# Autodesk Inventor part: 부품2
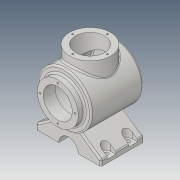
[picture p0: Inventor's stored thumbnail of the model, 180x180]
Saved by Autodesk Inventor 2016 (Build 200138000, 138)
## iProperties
Created: 2017-04
Part Number: 부품2
Material: Generic
Document SubType Name: Modeling
Designer: Administrator
Density: 1 g/cm^3
Appearance: 눈
Author: Administrator
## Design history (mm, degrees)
sketch "스케치1"
  geometry: L1 (-60, 2.834)-(-60, 12.834); L2 (-60, 12.834)-(-17.156, 42.834); L3 (-17.156, 42.834)-(17.156, 42.834); L4 (17.156, 42.834)-(60, 12.834); L5 (60, 12.834)-(60, 2.834); L6 (60, 2.834)-(-60, 2.834); 1 further point
  constraints: 12 end point, 2 perpendicular, 1 parallel, 1 vertical
  dimensions: "d0" = 120 distance of L5.end L1.start; "d1" = 10 distance of L4.end L5.end; "d2" = 10 distance of L1.start L1.end; "d3" = 55 deg angle of L2 L1; "d4" = 55 deg angle of L5 L4; "d5" = 40 distance between parallel lines of L6 L3; "d25" = 60 distance from line of point (0, 0) L1
extrude "돌출1" new body sketch "스케치1" stored distance "d6" = 80; taper "d7" = 0 deg
sketch "스케치2"
  geometry: L1 (42.834, -40)-(2.834, -40) reference; L2 (2.834, -40)-(2.834, 40) reference; L3 (2.834, 40)-(42.834, 40) reference; L4 (42.834, 40)-(42.834, -40) reference; L5 (84.834, -60)-(84.834, 48); L6 (84.834, 48)-(134.834, 48); L7 (134.834, 48)-(134.834, -47.617); L8 (134.834, -60)-(84.834, -60); L9 (116.006, 53)-(59.177, 53); L10 (84.834, 48)-(84.834, 65.284); A1 r 113 centre (84.037, 53.322) between (84.834, -59.675) and (134.834, -47.617); 1 further point
  constraints: 12 end point, 3 perpendicular, 2 point on circle, 2 vertical, 1 centre point, 1 horizontal, 1 point on line
  dimensions: "d8" = 108 distance of L6.end L8.start; "d9" = 82 distance between parallel lines of L2 L5; "d10" = 100 diameter of L7 L5; "d11" = 8 distance between parallel lines of L3 L6; "d12" = 113 distance between parallel lines of L8 L9; "d16" = 113 radius of A1
revolve "회전1" sketch "스케치2" stored, may be unused: angle "d17" = 90 deg
sketch "스케치3"
  geometry: C1 r 50 at (0, 0) reference; C2 r 38 at (0, 0); 1 further point
  constraints: 1 centre point, 1 coincident
  dimensions: "d18" = 76 diameter of C2
extrude "돌출2" join sketch "스케치3" distance "d19" = 12; taper "d20" = 0 deg
node "작업 평면1"
sketch "스케치4"
  geometry: C1 r 38 at (60, -40); 1 further point
  constraints: 1 centre point, 1 coincident
  dimensions: "d22" = 76 diameter of C1
extrude "돌출3" join sketch "스케치4" stored distance "d23" = 12; taper "d24" = 0 deg
sketch "스케치5"
  geometry: L1 (-21.584, 39.732)-(-60, 12.834) reference; L2 (-60, 12.834)-(-60, 2.834) reference; L3 (-60, 2.834)-(60, 2.834) reference; L4 (60, 2.834)-(60, 12.834) reference; L5 (60, 12.834)-(21.584, 39.732) reference; A1 r 50 centre (0, 84.834) between (-21.584, 39.732) and (21.584, 39.732) reference; 1 further point
sketch "스케치6"
  geometry: L1 (-60, 2.834)-(60, 2.834) reference; C1 r 18 at (0, 2.834); 1 further point
  constraints: 1 centre point, 1 midpoint
  dimensions: "d26" = 36 diameter of C1
extrude "돌출4" cut sketch "스케치6" stored distance "d27" = 12; taper "d28" = 0 deg
node "작업 평면2"
sketch "스케치7"
  geometry: L1 (-87.129, -7.617)-(-87.129, 88) reference; L2 (-87.129, 88)-(-32.871, 88) reference; L3 (-32.871, 88)-(-32.871, -7.617) reference; L4 (-38.416, 0)-(-38.416, 80) reference; L5 (0, 80)-(-38.416, 80) reference; L6 (0, 80)-(0, 0) reference; L7 (-38.416, 0)-(0, 0) reference; L8 (-10, 52)-(0, 52); L9 (-10, 68)-(0, 68); L10 (-10, 28)-(0, 28); L11 (-10, 12)-(0, 12); A1 r 8 centre (-10, 60) between (-10, 68) and (-10, 52); A2 r 8 centre (-10, 20) between (-10, 28) and (-10, 12); 1 further point
  constraints: 8 end point, 4 point on circle, 4 point on line, 3 horizontal, 2 centre point, 1 horizontal alignment, 1 perpendicular, 1 tangent
  dimensions: "d30" = 16 diameter of A1; "d31" = 16 diameter of A2; "d32" = 20 vertical distance of point (-60, 40) A1.centre; "d33" = 20 vertical distance of A2.centre point (-60, 40); "d34" = 10 distance from line of L6 A2.centre; "d35" = 10 distance from line of L6 A1.centre
extrude "돌출5" cut sketch "스케치7" distance "d36" = 34; taper "d37" = 0 deg
sketch "스케치8"
  geometry: A1 r 8 centre (-10, -60) between (-10, -52) and (-10, -68) reference; 1 further point
hole "구멍1" sketch "스케치8" at (-10, -60) diameter "d38" = 8; stored, may be unused: countersink angle "d42" = 90 deg, drill point angle "d44" = 118 deg; dims "d39" = 6, "d40" = 4, "d41" = 2, "d43" = 8
sketch "스케치9"
  geometry: A1 r 8 centre (-10, -20) between (-10, -12) and (-10, -28) reference; 1 further point
hole "구멍2" sketch "스케치9" at (-10, -20) diameter "d45" = 8; stored, may be unused: countersink angle "d49" = 90 deg, drill point angle "d51" = 118 deg; dims "d46" = 6, "d47" = 4, "d48" = 2, "d50" = 8
node "작업 평면3"
sketch "스케치10"
  geometry: L1 (-20, 120)-(-8, 120) reference; L2 (-8, 120)-(-8, 132) reference; L3 (-8, 132)-(2, 132) reference; L4 (2, 132)-(2, 147) reference; L5 (2, 147)-(78, 147) reference; L6 (78, 147)-(78, 132) reference; L7 (78, 132)-(87.617, 132) reference; L8 (87.617, 32)-(80, 32) reference; L9 (80, 32)-(80, 18) reference; L10 (80, 18)-(0, 18) reference; L11 (0, 18)-(0, 32) reference; L12 (0, 32)-(-8, 32) reference; L13 (-8, 32)-(-8, 44) reference; L14 (-8, 44)-(-20, 44) reference; L15 (-20, 44)-(-20, 120) reference; L16 (-20, 120)-(-20, 44) reference; L17 (-20, 82)-(89.675, 82); L18 (79.894, 122)-(5, 122); L19 (2, 119)-(2, 109); L20 (2, 109)-(-20, 109); A1 r 113 centre (-13.322, 82.797) between (87.617, 32) and (99.675, 82) reference; A2 r 113 centre (-13.322, 81.203) between (99.675, 82) and (87.617, 132) reference; A3 r 103 centre (-13.322, 82.797) between (89.675, 82) and (82.691, 120.086); A4 r 102.411 centre (-13.322, 81.203) between (80.713, 40.64) and (82.092, 44); A5 r 3 centre (5, 119) between (5, 122) and (2, 119); A6 r 3 centre (79.894, 119) between (82.691, 120.086) and (79.894, 122); 2 further points
  constraints: 9 point on circle, 8 end point, 4 centre point, 4 tangent, 3 point on line, 2 perpendicular, 1 equal radius, 1 horizontal, 1 midpoint
  dimensions: "d52" = 22 distance of L19.end L20.end; "d55" = 10 radial gap between concentric circles of A1 A3; "d56" = 54 diameter of L20 L17; "d57" = 80 diameter of L18 L17; "d58" = 3 radius of A5
revolve "회전2" sketch "스케치10" stored, may be unused: angle "d59" = 90 deg
sketch "스케치11"
  geometry: C1 r 38 at (0, 0) reference; C2 r 27 at (0, 0)
  constraints: 1 centre point, 1 coincident
  dimensions: "d60" = 54 diameter of C2
extrude "돌출6" cut sketch "스케치11" stored distance "d61" = 34; taper "d62" = 0 deg; dims "d81" = 40
sketch "스케치12"
  geometry: C1 r 27 at (0, 0) reference; 2 further points
  dimensions: "d63" = 32.5 distance of C1.centre point (0, 32.5)
hole "구멍3" sketch "스케치12" at (0, 32.5) diameter "d64" = 3.242; stored, may be unused: countersink angle "d68" = 90 deg, drill point angle "d70" = 118 deg; dims "d65" = 8, "d66" = 4, "d67" = 2, "d69" = 10
node "작업축1"
sketch "스케치13"
  geometry: 1 further point
hole "구멍4" sketch "스케치13" at (0, 32.15) diameter "d74" = 3.242; stored, may be unused: countersink angle "d78" = 90 deg, drill point angle "d80" = 118 deg; dims "d75" = 8, "d76" = 4, "d77" = 2, "d79" = 10
node "작업축2"
fillet "모깎기1" dims "d84" = 3
fillet "모깎기2" dims "d85" = 3
fillet "모깎기3" dims "d86" = 3
node "작업 평면4"
node "솔리드1"
mirror "대칭1"
pattern_circular "원형 패턴1" dims angle "d72" = 360 deg
pattern_circular "원형 패턴2" dims angle "d82" = 360 deg
node "투영된 루프1"
node "절단 모서리 투영1"
node "절단 모서리 투영2"
node "절단 모서리 투영3"
other parameters: "d15" = 226, "d21" = -147
